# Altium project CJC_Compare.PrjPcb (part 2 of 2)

## Sheet MCU.SchDoc
size 431 x 279 mm; Date: Not shown in title block; ApprovedBy: Not shown in title block; CheckedBy: Not shown in title block; Author: Not shown in title block; CompanyName: Not shown in title block; Engineer: Not shown in title block; Organization: Not shown in title block; Address1: Not shown in title block; Address2: Not shown in title block; Address3: Not shown in title block; Address4: Not shown in title block; DocumentNumber: 8; Revision: Use project parameter SCH_Rev; SheetNumber: 8; SheetTotal: 9; PageSetup: Record=PageOptions¦CenterHorizontal=True¦CenterVertical=True¦PrintScale=1.00¦XCorrection=1.00¦YCorrection=1.00¦PrintKind=0¦BorderSize=5000000¦LeftOffset=0¦BottomOffset=0¦Orientation=2¦PaperLength=1000¦PaperWidth=1000¦Scale=100¦PaperSource=15¦PrintQuality=600¦MediaType=1¦DitherType=10¦PaperKind=Letter¦PrintScaleMode=1
Used 3 times, as channels 1, 3, 4. Parts and nets are listed once, with the designators drawn on the sheet.
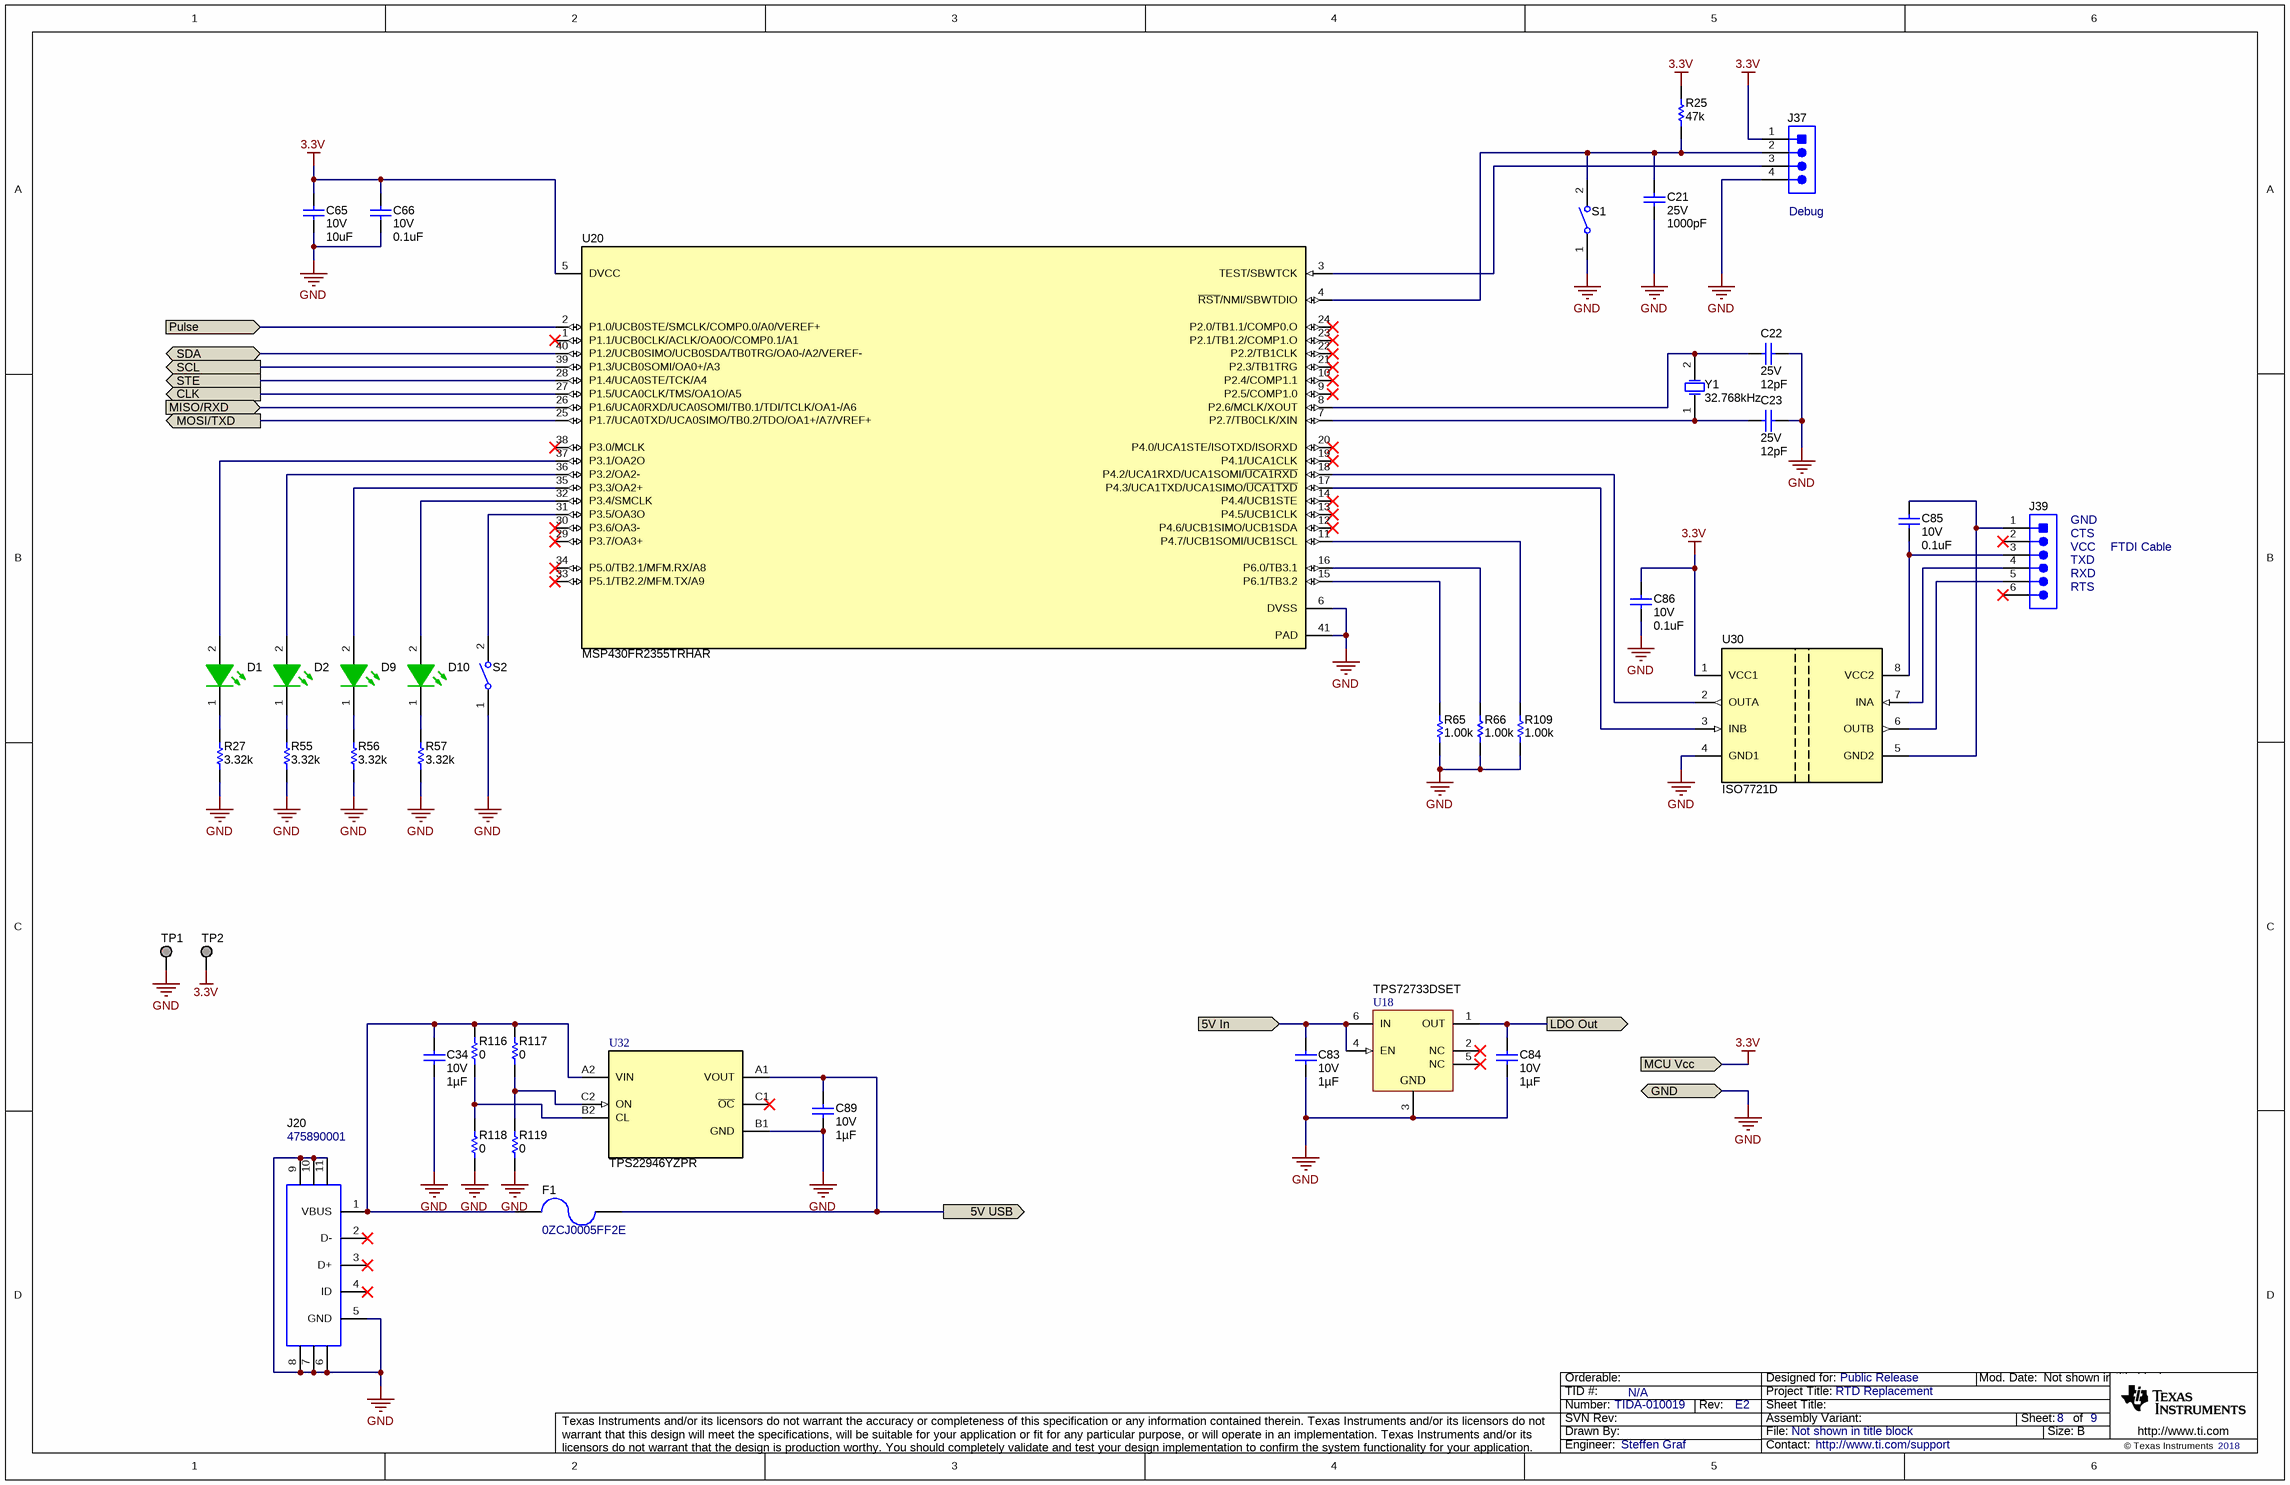
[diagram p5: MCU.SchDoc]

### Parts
C21  VDC_V: 25V  ValueDisplayed: 1000pF  [0603]  (hidden comment: C0603C102K3GACTU)
C22  VDC_V: 25V  ValueDisplayed: 12pF  [0402]  (hidden comment: GRM1555C1E120JA01D)
C23  VDC_V: 25V  ValueDisplayed: 12pF  [0402]  (hidden comment: GRM1555C1E120JA01D)
C34  VDC_V: 10V  ValueDisplayed: 1µF  [0603]  (hidden comment: CL10B105KP8NNNC)
C65  VDC_V: 10V  ValueDisplayed: 10uF  [0805_HV]  (hidden comment: 885012207026)
C66  VDC_V: 10V  ValueDisplayed: 0.1uF  [0603]  (hidden comment: 885012206020)
C83  VDC_V: 10V  ValueDisplayed: 1µF  [0603]  (hidden comment: CL10B105KP8NNNC)
C84  VDC_V: 10V  ValueDisplayed: 1µF  [0603]  (hidden comment: CL10B105KP8NNNC)
C85  VDC_V: 10V  ValueDisplayed: 0.1uF  [0603]  (hidden comment: 885012206020)
C86  VDC_V: 10V  ValueDisplayed: 0.1uF  [0603]  (hidden comment: 885012206020)
C89  VDC_V: 10V  ValueDisplayed: 1µF  [0603]  (hidden comment: CL10B105KP8NNNC)
D1  150040GS73240  [WL-SMCC_0402_Green]  (value not drawn)
D2  150040GS73240  [WL-SMCC_0402_Green]  (value not drawn)
D9  150040GS73240  [WL-SMCC_0402_Green]  (value not drawn)
D10  150040GS73240  [WL-SMCC_0402_Green]  (value not drawn)
F1  0ZCJ0005FF2E  [FUSE_0ZCJ_085]
J20  475890001  [Molex_0475890001]
J37  61300411121  [WURTH_61300411121]  (value not drawn)
J39  61300611121  [WURTH_61300611121]  (value not drawn)
R25  ValueDisplayed: 47k  [0402]  (hidden comment: CRCW040247K0JNED)
R27  ValueDisplayed: 3.32k  [0402]  (hidden comment: CRCW04023K32FKED)
R55  ValueDisplayed: 3.32k  [0402]  (hidden comment: CRCW04023K32FKED)
R56  ValueDisplayed: 3.32k  [0402]  (hidden comment: CRCW04023K32FKED)
R57  ValueDisplayed: 3.32k  [0402]  (hidden comment: CRCW04023K32FKED)
R65  ValueDisplayed: 1.00k  [0603]  (hidden comment: CRCW06031K00FKEA)
R66  ValueDisplayed: 1.00k  [0603]  (hidden comment: CRCW06031K00FKEA)
R109  ValueDisplayed: 1.00k  [0603]  (hidden comment: CRCW06031K00FKEA)
R116  ValueDisplayed: 0  [0402]  (hidden comment: CRCW04020000Z0EDHP)
R117  ValueDisplayed: 0  [0402]  (hidden comment: CRCW04020000Z0EDHP)
R118  ValueDisplayed: 0  [0402]  (hidden comment: CRCW04020000Z0EDHP)
R119  ValueDisplayed: 0  [0402]  (hidden comment: CRCW04020000Z0EDHP)
S1  434121025816  [SW_434121025816]  (value not drawn)
S2  434121025816  [SW_434121025816]  (value not drawn)
TP1  S2751-46R  [Harwin_S2751-46R]  (value not drawn)  (no BOM)
TP2  S2751-46R  [Harwin_S2751-46R]  (value not drawn)  (no BOM)
U18  TPS72733DSET  [DSE0006A]
U20  MSP430FR2355TRHAR  [RHA0040E]
U30  ISO7721D  [D0008B_HV]
U32  TPS22946YZPR  [YZP0006ADAD]
Y1  Frequency_Fixed: 32.768kHz  [ECS_ECX_31B]  (hidden comment: ECS-.327-12.5-34B-TR)

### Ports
5V In (in), 5V USB (out), CLK (out), GND (bidir), LDO Out (out), MCU Vcc (in), MISO/RXD (in), MOSI/TXD (out), Pulse (in), SCL (out), SDA (bidir), STE (out)

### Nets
3.3V: C65.1 C66.1 C86.1 J37.1 R25.2 TP2.1 U20.5(DVCC) U30.1(VCC1) ; port MCU Vcc
GND: C21.2 C22.2 C23.2 C34.2 C65.2 C66.2 C83.2 C84.2 C86.2 C89.2 J20.5(GND) J20.6 J20.7 J20.8 J20.9 J20.10 J20.11 J37.4 R27.1 R55.1 R56.1 R57.1 R65.1 R66.1 R109.1 R118.1 R119.1 S1.1 S2.1 TP1.1 U18.3(GND) U20.6(DVSS) U20.41(PAD) U30.4(GND1) U32.B1(GND) ; port GND
5V In: C83.1 U18.4(EN) U18.6(IN) ; port 5V In
5V USB: C89.1 F1.1 U32.A1(VOUT) ; port 5V USB
CLK: U20.27(P1.5/UCA0CLK/TMS/OA1O/A5) ; port CLK
LDO Out: C84.1 U18.1(OUT) ; port LDO Out
MISO/RXD: U20.26(P1.6/UCA0RXD/UCA0SOMI/TB0.1/TDI/TCLK/OA1-/A6) ; port MISO/RXD
MOSI/TXD: U20.25(P1.7/UCA0TXD/UCA0SIMO/TB0.2/TDO/OA1+/A7/VREF+) ; port MOSI/TXD
Pulse: U20.2(P1.0/UCB0STE/SMCLK/COMP0.0/A0/VEREF+) ; port Pulse
SCL: U20.39(P1.3/UCB0SOMI/OA0+/A3) ; port SCL
SDA: U20.40(P1.2/UCB0SIMO/UCB0SDA/TB0TRG/OA0-/A2/VEREF-) ; port SDA
STE: U20.28(P1.4/UCA0STE/TCK/A4) ; port STE
NetC21_1: C21.1 J37.2 R25.1 S1.2 U20.4(~{RST}/NMI/SBWTDIO)
NetC22_1: C22.1 U20.8(P2.6/MCLK/XOUT) Y1.2(OSC2)
NetC23_1: C23.1 U20.7(P2.7/TB0CLK/XIN) Y1.1(OSC1)
NetC34_1: C34.1 F1.2 J20.1(VBUS) R116.2 R117.2 U32.A2(VIN)
NetC85_1: C85.1 J39.1 U30.5(GND2)
NetC85_2: C85.2 J39.3 U30.8(VCC2)
NetD1_1: D1.1(K) R27.2
NetD1_2: D1.2(A) U20.37(P3.1/OA2O)
NetD2_1: D2.1(K) R55.2
NetD2_2: D2.2(A) U20.36(P3.2/OA2-)
NetD9_1: D9.1(K) R56.2
NetD9_2: D9.2(A) U20.35(P3.3/OA2+)
NetD10_1: D10.1(K) R57.2
NetD10_2: D10.2(A) U20.32(P3.4/SMCLK)
NetJ37_3: J37.3 U20.3(TEST/SBWTCK)
NetJ39_4: J39.4 U30.7(INA)
NetJ39_5: J39.5 U30.6(OUTB)
NetR65_2: R65.2 U20.15(P6.1/TB3.2)
NetR66_2: R66.2 U20.16(P6.0/TB3.1)
NetR109_2: R109.2 U20.11(P4.7/UCB1SOMI/UCB1SCL)
NetR116_1: R116.1 R118.2 U32.B2(CL)
NetR117_1: R117.1 R119.2 U32.C2(ON)
NetS2_2: S2.2 U20.31(P3.5/OA3O)
NetU20_17: U20.17(P4.3/UCA1TXD/UCA1SIMO/~{UCA1TXD}) U30.3(INB)
NetU20_18: U20.18(P4.2/UCA1RXD/UCA1SOMI/~{UCA1RXD}) U30.2(OUTA)

Not connected (* = marked no-connect by the designer): J20 2(D-)* 3(D+)* 4(ID)*; J39 2* 6*; U18 2(NC)* 5(NC)*; U20 1(P1.1/UCB0CLK/ACLK/OA0O/COMP0.1/A1)* 9(P2.5/COMP1.0)* 10(P2.4/COMP1.1)* 12(P4.6/UCB1SIMO/UCB1SDA)* 13(P4.5/UCB1CLK)* 14(P4.4/UCB1STE)* 19(P4.1/UCA1CLK)* 20(P4.0/UCA1STE/ISOTXD/ISORXD)* 21(P2.3/TB1TRG)* 22(P2.2/TB1CLK)* 23(P2.1/TB1.2/COMP1.O)* 24(P2.0/TB1.1/COMP0.O)* 29(P3.7/OA3+)* 30(P3.6/OA3-)* 33(P5.1/TB2.2/MFM.TX/A9)* 34(P5.0/TB2.1/MFM.RX/A8)* 38(P3.0/MCLK)*; U32 C1(~{OC})*

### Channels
1: designators end in _1; ports 5V In=NetC83_1_1 5V USB=NetC89_1_1 CLK=NetU20_1_27 GND=GND LDO Out=NetC84_1_1 MCU Vcc=3.3V MISO/RXD=NetU20_1_26 MOSI/TXD=NetU20_1_25 Pulse=NetJ36_1 SCL=NetJ22_14 SDA=NetJ36_2 STE=NetU20_1_28
3: designators end in _3; ports 5V In=NetC83_3_1 5V USB=NetC89_3_1 CLK=NetU20_3_27 GND=GND LDO Out=NetC84_3_1 MCU Vcc=3.3V MISO/RXD=NetJ24_10 MOSI/TXD=NetJ24_12 Pulse=NetU20_3_2 SCL=NetU20_3_39 SDA=NetU20_3_40 STE=NetJ24_14
4: designators end in _4; ports 5V In=NetC83_4_1 5V USB=NetC89_4_1 CLK=NetU20_4_27 GND=GND LDO Out=NetC84_4_1 MCU Vcc=3.3V MISO/RXD=NetJ8_10 MOSI/TXD=NetJ8_12 Pulse=NetU20_4_2 SCL=NetU20_4_39 SDA=NetU20_4_40 STE=NetJ8_14

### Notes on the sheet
- (near J37) Debug
- (near J39) GND
- (near J39) CTS
- (near J39) VCC
- (near J39) TXD
- FTDI Cable
- (near J39) RXD
- (near J39) RTS

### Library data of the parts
C21 = CMP-0006846-4: CAP, CERM, 1000 pF, 25 V, +/- 10%, C0G/NP0, 0603; Manufacturer: Kemet; TaMin_C: -55°C; Polarized: N; SizeAreaWB_mm2: 4.68; Value1: 0 ohm; U/M: EA; Value: 1000pF; TaMax_C: 125°C; SizeZ_mm: 1; SizeX_mm: 1.6; SizeY_mm: 0.8; SizeArea_mm2: 1.28; Cap_F: 1nF; AEC Category: Q200; ESR_ohm: 0; IRMS_A: 0A
C22 C23 = CMP-0006375-2: CAP, CERM, 12 pF, 25 V, +/- 5%, C0G/NP0, 0402; Manufacturer: MuRata; TaMin_C: -55°C; Polarized: N; SizeAreaWB_mm2: 3; Value1: Unknown; U/M: EA; Value: 12pF; TaMax_C: 125°C; SizeZ_mm: 0.6; SizeX_mm: 1; SizeY_mm: 0.5; AEC Category: Q200
C34 C83 C84 C89 = CMP-0082011-1: CAP, CERM, 1 µF, 10 V,+/- 10%, X7R, 0603; Manufacturer: Samsung; SizeAreaWB_mm2: 4.68; SizeArea_mm2: 1.28; AEC Qualified: N; AEC Category: Q200; Value: 1uF; TaMax_C: 125°C; SizeZ_mm: 1; TaMin_C: -55°C; SizeY_mm: 0.8; U/M: EA; SizeX_mm: 1.6
C65 = CMP-0007691-2: CAP, CERM, 10 uF, 10 V, +/- 10%, X7R, 0805; Manufacturer: Wurth Elektronik; TaMin_C: -55°C; Polarized: N; SizeAreaWB_mm2: 6.75; Value1: Unknown; U/M: EA; Value: 10uF; TaMax_C: 125°C; SizeZ_mm: 1.45; SizeX_mm: 2; SizeY_mm: 1.25; Cap_Case: 0805; SizeArea_mm2: 2.5; Cap_F: 10µF; AEC Category: Q200
C66 C85 C86 = CMP-0064931-4: CAP, CERM, 0.1 uF, 10 V,+/- 10%, X7R, 0603; Manufacturer: Wurth Elektronik; TaMin_C: -55°C; Polarized: N; SizeAreaWB_mm2: 4.68; Value1: Unknown; U/M: EA; Value: 0.1uF; TaMax_C: 125°C; SizeZ_mm: 1; SizeX_mm: 1.6; SizeY_mm: 0.8; SizeArea_mm2: 1.28; Cap_F: 100nF; AEC Category: Q200
D1 D2 D9 D10 = CMP-0081765-2: LED, Green, SMD; Manufacturer: Wurth Elektronik; Io_A: 20mA; Power_TotalModule: 99mW; Vr_V: 5V; SizeAreaWB_mm2: 3; Tjmax_C: 95°C; Value1: 0.099W; Angle: 120; SizeZ_mm: 0.5; SizeX_mm: 1; Ir_A: 10µA; Vf_V: 3.2V; Type: InGaN
F1 = CMP-0081903-1: Fuse, 0.05 A, 60 VDC, SMD; Manufacturer: Bel Fuse; Fuse Technology: Board Mount; SizeAreaWB_mm2: 11.2625; SizeArea_mm2: 5.3625; Fuse Speed: Fast; Irating_A: 50mA; TaMax_C: 85°C; SizeZ_mm: 0.85; TaMin_C: -40°C; VDC_V: 60V; SizeY_mm: 1.65; SizeX_mm: 3.25
J20 = CMP-0055301-1: Connector, Receptacle, Micro-USB Type AB, R/A, Bottom Mount SMT; Manufacturer: Molex; CNHeader: FALSE; Green_Lifecycle: Active; Gender: Female; Green_REACh: Passed; CompType: USB; CT: TRUE
J37 = CMP-0054798-2: Header, 2.54 mm, 4x1, Gold, TH; Manufacturer: Wurth Elektronik; Pitch_mm: 2.54; Gender: Male; Row_Count: 1; Cert_UL: Y; Shrouded: N
J39 = CMP-0054801-2: Header, 2.54 mm, 6x1, Gold, TH; Manufacturer: Wurth Elektronik; Cert_UL: Y; Gender: Male; Row_Count: 1; Shrouded: N; Pitch_mm: 2.54
R25 = CMP-0026935-3: RES, 47 k, 5%, 0.063 W, AEC-Q200 Grade 0, 0402; Manufacturer: Vishay-Dale; Power_W: 63mW; TempCo: 200 ppm/C; Value_Code: 47k0; Value: 47k; EIA_Code: E24; SizeX_mm: 1; SizeY_mm: 0.5; SizeZ_mm: 0.6; Value2: 0.063W; AEC Qualified: Y; VDC_V: 50V; AEC Category: Q200; AEC Grade: 0
R27 R55-R57 = CMP-0026333-2: RES, 3.32 k, 1%, 0.063 W, AEC-Q200 Grade 0, 0402; Manufacturer: Vishay-Dale; Power_W: 63mW; TempCo: 100 ppm/C; Value_Code: 3k32; Value: 3.32k; EIA_Code: E96; SizeX_mm: 1; SizeY_mm: 0.5; SizeZ_mm: 0.6; Value2: 0.063W; AEC Qualified: Y; VDC_V: 50V; AEC Category: Q200; AEC Grade: 0
R65 R66 R109 = CMP-0022109-5: RES, 1.00 k, 1%, 0.1 W, AEC-Q200 Grade 0, 0603; Manufacturer: Vishay-Dale; Power_W: 100mW; TempCo: 100 ppm/C; Value_Code: 1k00; Value: 1.00k; EIA_Code: E96; Res_ohm: 1k; SizeX_mm: 1.6; SizeY_mm: 0.8; SizeZ_mm: 1; Value2: 0.1W; SizeArea_mm2: 1.28; AEC Qualified: Y; VDC_V: 75V; AEC Category: Q200; AEC Grade: 0
R116-R119 = CMP-0081856-1: RES, 0, 0%, 0.2 W, AEC-Q200 Grade 0, 0402; Manufacturer: Vishay-Dale; SizeAreaWB_mm2: 3; SizeArea_mm2: 0.5; AEC Qualified: Y; AEC Category: Q200; Value: 0; SizeZ_mm: 0.6; Power_W: 200mW; VDC_V: 50V; Value2: 0.2W; SizeX_mm: 1
S1 S2 = CMP-0002196-2: Switch, Tactile, SPST, 12 V, SMD; Manufacturer: Wurth Elektronik; CurrentRating_mA: 50A; PositionCount: 1; VDC_V: 12V; SwitchFunction: Off-On
TP1 TP2 = CMP-0003968-1: Test Point, SMT; Manufacturer: Harwin
U18 = CMP-0036117-3: 250-mA, Ultralow IQ, Fast Transient Response, RF Low-Dropout Linear Regulator,  DSE0006A (WSON-6); Manufacturer: Texas Instruments; Vin(Min)(V): 2; Vout Adj(Max)(V): 3.3; Vin(Max)(V): 5.5; Eco-Plan: Green (RoHS & no Sb/Br); Rating: Catalog; Iq(Typ)(mA): 0.008; Iout(Max)(A): 0.25; Vdo(Typ)(mV): 130; AEC Category: Q200; AEC Qualified: N; CompType: IC; SizeAreaWB_mm2: 6.25; SizeArea_mm2: 2.25; SizeX_mm: 1.5; SizeZ_mm: 0.8
U20 = CMP-0081780-1: Mixed-Signal Microcontroller, RHA0040E (VQFN-40); Alternate PartNumber: MSP430FR2355TRHAT; Alternate Manufacturer: Texas Instruments; SizeAreaWB_mm2: 66.4225; Rating: Catalog; SizeZ_mm: 1; SizeX_mm: 6.15; SizeArea_mm2: 37.8225; CompType: IC; AEC Qualified: N; AEC Category: Q200
U30 = CMP-0085670-1: High Speed, Robust EMC Reinforced Dual-Channel Digital Isolator, D0008B (SOIC-8); Manufacturer: Texas Instruments; Alternate PartNumber: ISO7721DR; SizeX_mm: 6; SizeAreaWB_mm2: 55.2; AEC Qualified: N; SizeArea_mm2: 29.4; CompType: IC; Rating: Catalog; SizeZ_mm: 1.75; SizeY_mm: 4.9; AEC Category: Q200
U32 = CMP-0034332-1: Ultra-Low Power, Low Input Voltage, Current Limited Load Switch, 300 mOhms rDS(On), -40 to 85 degC, 6-pin DSBGA (YZP), Green (RoHS & no Sb/Br); Manufacturer: Texas Instruments; Vin(Min)(V): 1.62; rDS(on) per FET(Typ)(mOhms): 300; Vin(Max)(V): 5.5; Enable/Shutdown: Active High; Number of FETs: 1; SubFamily: Current Limited Switch; Adjustable Current Limit(Min)(A): 0.155, 0.07, 0.03
Y1 = CMP-0078856-1: Crystal, 32.768 KHz, 20 ppm, SMD; Manufacturer: ECS Inc.; SizeAreaWB_mm2: 10.5; SizeArea_mm2: 4.8; Frequency Tolerance: 20 ppm; AEC Category: Q200; TaMax_C: 85°C; SizeZ_mm: 0.9; TaMin_C: -40°C; SizeY_mm: 1.5; SizeX_mm: 3.2

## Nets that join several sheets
3.3V: TC_INA_ADS7142 (10 pins), 1 (8 pins)
3.3V: TC_RTD_CJC_QFN (J24.6), 3 (8 pins)
3.3V: TC_LMT70_CJC (J8.6), 4 (8 pins)
GND: TC_INA_ADS7142 (8 pins), 1 (35 pins)
GND: TC_RTD_CJC_QFN (J24.20), 3 (35 pins)
GND: TC_LMT70_CJC (J8.20), 4 (35 pins)
NetC83_1_1: TC_INA_ADS7142 (J22.4), 1 (C83_1.1 U18_1.4 U18_1.6)
NetC83_3_1: TC_RTD_CJC_QFN (J24.4), 3 (C83_3.1 U18_3.4 U18_3.6)
NetC83_4_1: TC_LMT70_CJC (J8.4), 4 (C83_4.1 U18_4.4 U18_4.6)
NetC84_1_1: TC_INA_ADS7142 (J22.8), 1 (C84_1.1 U18_1.1)
NetC84_3_1: TC_RTD_CJC_QFN (J24.8), 3 (C84_3.1 U18_3.1)
NetC84_4_1: TC_LMT70_CJC (J8.8), 4 (C84_4.1 U18_4.1)
NetC89_1_1: TC_INA_ADS7142 (J22.2), 1 (C89_1.1 F1_1.1 U32_1.A1)
NetC89_3_1: TC_RTD_CJC_QFN (J24.2), 3 (C89_3.1 F1_3.1 U32_3.A1)
NetC89_4_1: TC_LMT70_CJC (J8.2), 4 (C89_4.1 F1_4.1 U32_4.A1)
NetJ8_10: TC_LMT70_CJC (J8.10), 4 (U20_4.26)
NetJ8_12: TC_LMT70_CJC (J8.12), 4 (U20_4.25)
NetJ8_14: TC_LMT70_CJC (J8.14), 4 (U20_4.28)
NetJ22_14: TC_INA_ADS7142 (J22.14 J36.3 R112.1 U23.1), 1 (U20_1.39)
NetJ24_10: TC_RTD_CJC_QFN (J24.10), 3 (U20_3.26)
NetJ24_12: TC_RTD_CJC_QFN (J24.12), 3 (U20_3.25)
NetJ24_14: TC_RTD_CJC_QFN (J24.14), 3 (U20_3.28)
NetJ36_1: TC_INA_ADS7142 (J36.1 Q3.3 R86.1), 1 (U20_1.2)
NetJ36_2: TC_INA_ADS7142 (5 pins), 1 (U20_1.40)

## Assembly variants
001: not fitted C22_0 C22_1 C22_2 C22_3 C22_4 C22_5 C23_0 C23_1 C23_2 C23_3 C23_4 C23_5 C87 C88 C90 F1_0 F1_1 F1_2 F1_3 F1_4 F1_5 FID1 FID2 FID3 FID4 FID5 FID6 R65_0 R65_1 R65_2 R65_3 R66_0 R66_1 R66_4 R66_5 R73 R75 R75 R83 R109_0 R109_2 R109_4 R116_0 R116_1 R116_2 R116_3 R116_4 R116_5 R118_0 R118_1 R118_2 R118_3 R118_4 R118_5 R119_0 R119_1 R119_2 R119_3 R119_4 R119_5 Y1_0 Y1_1 Y1_2 Y1_3 Y1_4 Y1_5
